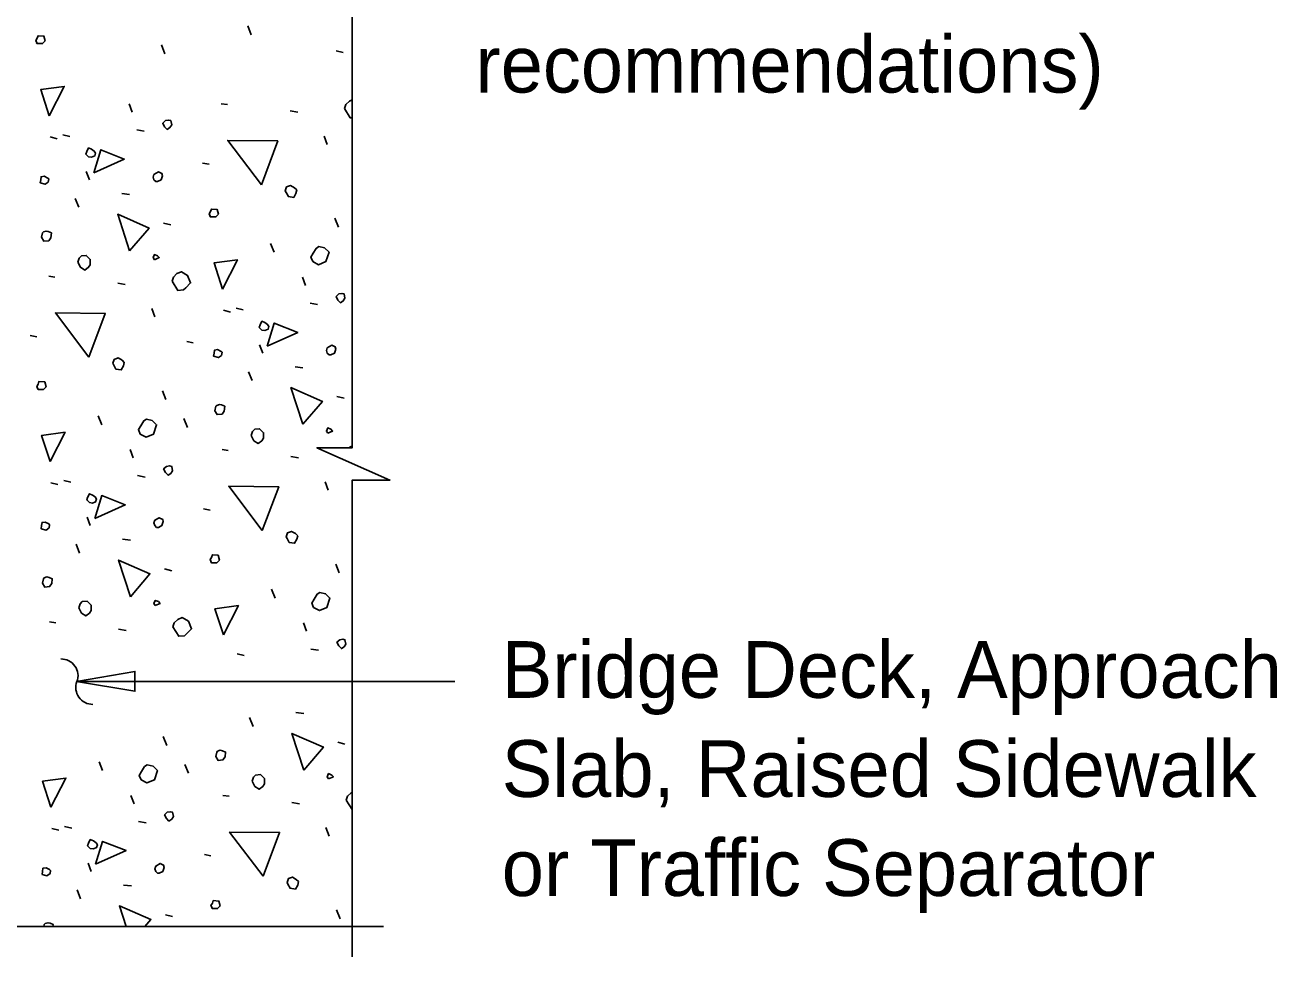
# Model space of a CAD drawing. Extents: x 0 to 15.4, y 0 to 9.7.
# Drawn here: x 5 to 6.668, y 1.924 to 3.173 of the extents above; entities that cross this region are included whole.
import ezdxf

# ---------------------------------------------------------------- set-up
doc = ezdxf.new("R2010")
doc.units = 0
doc.layers.add('Dimension', color=7, linetype='Continuous')
doc.layers.add('Miscellaneous', color=7, linetype='Continuous')

msp = doc.modelspace()

# ---------------------------------------------------------------- linework, layer by layer
at = {"layer": 'Dimension'}
msp.add_line((5.5721, 2.2981), (5.0679, 2.2981), dxfattribs=at)
for points in [[(5.4356, 3.1456), (5.4356, 3.4469), (5.4858, 3.4469), (5.3885, 3.49), (5.4356, 3.49), (5.4356, 4.0864)], [(5.4356, 1.931), (5.4356, 2.5663), (5.4858, 2.5663), (5.3885, 2.6094), (5.4356, 2.6094), (5.4356, 3.1456)], [(5.477, 1.9713), (4.8318, 1.9713), (4.8318, 2.0215), (4.7887, 1.9242), (4.7887, 1.9713), (4.2134, 1.9713)]]:
    msp.add_lwpolyline(points, dxfattribs=at)
msp.add_lwpolyline([(5.0679, 2.2981), (5.146, 2.2849), (5.146, 2.3113)], close=True, dxfattribs=at)
for centre, start, end in [((5.0477, 2.3056), 339.2893, 91.0165), ((5.0896, 2.2898), 159.2893, 271.0165)]:
    msp.add_arc(centre, 0.0224, start, end, dxfattribs=at)
at = {"layer": 'Miscellaneous'}
for p, q in [((5.3009, 3.1597), (5.2962, 3.1715)), ((5.186, 3.1344), (5.1813, 3.1462)), ((5.4141, 3.1385), (5.4235, 3.1361)), ((5.1424, 3.0566), (5.1383, 3.0678)), ((5.2608, 3.0678), (5.2691, 3.0666)), ((5.3528, 3.0584), (5.3628, 3.0566)), ((5.0328, 3.0236), (5.0422, 3.0212)), ((5.0499, 3.0265), (5.0593, 3.0242)), ((5.1483, 3.033), (5.1583, 3.0312)), ((5.4023, 3.0136), (5.3981, 3.0248)), ((5.2361, 2.9888), (5.2449, 2.9871)), ((5.0852, 2.9664), (5.0811, 2.9776)), ((5.0711, 2.9299), (5.0664, 2.9417)), ((5.1283, 2.9482), (5.1389, 2.947)), ((5.1842, 2.9087), (5.1937, 2.9063)), ((5.417, 2.9034), (5.4123, 2.9152)), ((5.3316, 2.8698), (5.3268, 2.8816)), ((5.031, 2.838), (5.0393, 2.8368)), ((5.3734, 2.8256), (5.3693, 2.8368)), ((5.123, 2.8285), (5.133, 2.8268)), ((5.1725, 2.7838), (5.1683, 2.795)), ((5.2638, 2.7926), (5.2732, 2.7902)), ((5.2809, 2.7955), (5.2903, 2.7932)), ((5.3793, 2.802), (5.3893, 2.8003)), ((5.0063, 2.759), (5.0151, 2.7572)), ((5.2149, 2.7508), (5.2237, 2.749)), ((5.3162, 2.7354), (5.3121, 2.7466)), ((5.3021, 2.6989), (5.2974, 2.7107)), ((5.3593, 2.7172), (5.3699, 2.716)), ((5.1872, 2.6736), (5.1825, 2.6854)), ((5.4152, 2.6777), (5.4247, 2.6753)), ((5.1017, 2.64), (5.097, 2.6518)), ((5.2161, 2.6364), (5.2113, 2.6482)), ((5.1436, 2.5958), (5.1395, 2.607)), ((5.262, 2.607), (5.2703, 2.6058)), ((5.3539, 2.5976), (5.364, 2.5958)), ((5.1495, 2.5722), (5.1595, 2.5704)), ((5.034, 2.5628), (5.0434, 2.5604)), ((5.0511, 2.5657), (5.0605, 2.5634)), ((5.4034, 2.5528), (5.3993, 2.564)), ((5.2373, 2.528), (5.2461, 2.5263)), ((5.0864, 2.5056), (5.0823, 2.5168)), ((5.1294, 2.4874), (5.14, 2.4862)), ((5.0723, 2.4691), (5.0676, 2.4809)), ((5.4182, 2.4426), (5.4135, 2.4544)), ((5.1854, 2.4479), (5.1949, 2.4455)), ((5.3327, 2.409), (5.328, 2.4208)), ((5.0322, 2.3772), (5.0405, 2.376)), ((5.3746, 2.3648), (5.3704, 2.376)), ((5.1241, 2.3677), (5.1342, 2.366)), ((5.3805, 2.3412), (5.3905, 2.3395)), ((5.2821, 2.3347), (5.2915, 2.3324)), ((5.3604, 2.2564), (5.371, 2.2552)), ((5.3033, 2.2381), (5.2986, 2.2499)), ((5.1884, 2.2128), (5.1837, 2.2246)), ((5.4164, 2.2169), (5.4258, 2.2145)), ((5.1029, 2.1792), (5.0982, 2.191)), ((5.2172, 2.1756), (5.2125, 2.1874)), ((5.1448, 2.135), (5.1406, 2.1462)), ((5.2632, 2.1462), (5.2715, 2.145)), ((5.3551, 2.1368), (5.3651, 2.135)), ((5.0352, 2.102), (5.0446, 2.0996)), ((5.0523, 2.1049), (5.0617, 2.1026)), ((5.1507, 2.1114), (5.1607, 2.1097)), ((5.4046, 2.092), (5.4005, 2.1032)), ((5.0876, 2.0448), (5.0835, 2.056)), ((5.2385, 2.0672), (5.2473, 2.0655)), ((5.0735, 2.0083), (5.0688, 2.0201)), ((5.1306, 2.0266), (5.1412, 2.0254)), ((5.1866, 1.9871), (5.196, 1.9847)), ((5.4194, 1.9818), (5.4146, 1.9936))]:
    msp.add_line(p, q, dxfattribs=at)
for points in [[(5.0157, 3.1479), (5.0228, 3.1479), (5.0263, 3.1515), (5.0246, 3.1579), (5.0169, 3.1585), (5.0157, 3.155), (5.0139, 3.152), (5.0157, 3.1479), (5.0145, 3.1491)], [(5.0316, 3.0519), (5.0204, 3.0866), (5.0517, 3.0908), (5.0316, 3.0519)], [(5.4356, 3.0729), (5.4317, 3.0713), (5.427, 3.0666), (5.4252, 3.0613)], [(5.4252, 3.0613), (5.4329, 3.0489), (5.4356, 3.0491)], [(5.1854, 3.0371), (5.189, 3.0336), (5.1925, 3.036), (5.1949, 3.0395), (5.1937, 3.0454), (5.1907, 3.046), (5.1866, 3.0454), (5.1831, 3.0419), (5.1854, 3.0371)], [(5.0841, 2.9971), (5.0882, 2.9965), (5.0923, 2.9982), (5.0935, 3.0018), (5.0917, 3.0047), (5.0882, 3.0071), (5.0841, 3.0089), (5.0817, 3.0041), (5.0805, 3.0006), (5.0841, 2.9971)], [(5.0911, 2.9759), (5.1006, 3.0065), (5.1318, 2.9941), (5.0911, 2.9759)], [(5.3145, 2.9599), (5.2697, 3.0189), (5.3363, 3.0183), (5.3145, 2.9599)], [(5.0198, 2.9623), (5.0263, 2.9605), (5.0304, 2.9635), (5.031, 2.9676), (5.0299, 2.9688), (5.0251, 2.9711), (5.021, 2.9706), (5.0204, 2.9664), (5.0198, 2.9623)], [(5.1736, 2.9641), (5.176, 2.9641), (5.1807, 2.9664), (5.1825, 2.9717), (5.1819, 2.9747), (5.1772, 2.977), (5.1713, 2.9735), (5.1701, 2.97), (5.1713, 2.9664), (5.1736, 2.9641)], [(5.3475, 2.9493), (5.3504, 2.944), (5.3575, 2.9429), (5.3604, 2.9482), (5.3616, 2.9529), (5.3587, 2.9558), (5.3534, 2.9588), (5.3481, 2.957), (5.3463, 2.9517), (5.3475, 2.9493)], [(5.1389, 2.8716), (5.123, 2.9205), (5.1648, 2.9022), (5.1389, 2.8716)], [(5.2467, 2.9169), (5.2538, 2.9169), (5.2573, 2.9205), (5.2555, 2.9269), (5.2479, 2.9275), (5.2467, 2.924), (5.2449, 2.9211), (5.2467, 2.9169), (5.2455, 2.9181)], [(5.0216, 2.8898), (5.0246, 2.8845), (5.031, 2.8851), (5.034, 2.8892), (5.0346, 2.8957), (5.0304, 2.8975), (5.0275, 2.8981), (5.024, 2.8969), (5.0228, 2.8957), (5.0216, 2.8898)], [(5.3828, 2.8574), (5.3905, 2.8533), (5.4005, 2.8574), (5.4046, 2.8698), (5.3987, 2.8757), (5.3911, 2.8775), (5.3875, 2.8751), (5.3834, 2.8686), (5.3805, 2.8633), (5.3828, 2.8574)], [(5.0699, 2.8568), (5.0735, 2.8498), (5.0794, 2.8462), (5.0841, 2.8498), (5.0864, 2.8533), (5.0864, 2.8604), (5.0811, 2.8657), (5.0746, 2.8651), (5.0717, 2.8621), (5.0699, 2.8568)], [(5.1719, 2.8598), (5.1784, 2.8627), (5.176, 2.8651), (5.1719, 2.8668), (5.1701, 2.8627), (5.1719, 2.8598)], [(5.2626, 2.8209), (5.2514, 2.8556), (5.2826, 2.8598), (5.2626, 2.8209)], [(5.1954, 2.8315), (5.2031, 2.8191), (5.2108, 2.8197), (5.2137, 2.8227), (5.2202, 2.8291), (5.2161, 2.8391), (5.2078, 2.8439), (5.2019, 2.8415), (5.1972, 2.8368), (5.1954, 2.8315)], [(5.4164, 2.8062), (5.4199, 2.8026), (5.4235, 2.805), (5.4258, 2.8085), (5.4247, 2.8144), (5.4217, 2.815), (5.4176, 2.8144), (5.4141, 2.8109), (5.4164, 2.8062)], [(5.0847, 2.7301), (5.0399, 2.7891), (5.1065, 2.7885), (5.0847, 2.7301)], [(5.3151, 2.7661), (5.3192, 2.7655), (5.3233, 2.7673), (5.3245, 2.7708), (5.3227, 2.7737), (5.3192, 2.7761), (5.3151, 2.7779), (5.3127, 2.7732), (5.3115, 2.7696), (5.3151, 2.7661)], [(5.3221, 2.7449), (5.3316, 2.7755), (5.3628, 2.7631), (5.3221, 2.7449)], [(5.2508, 2.7313), (5.2573, 2.7295), (5.2614, 2.7325), (5.262, 2.7366), (5.2608, 2.7378), (5.2561, 2.7402), (5.252, 2.7396), (5.2514, 2.7354), (5.2508, 2.7313)], [(5.4046, 2.7331), (5.407, 2.7331), (5.4117, 2.7354), (5.4135, 2.7407), (5.4129, 2.7437), (5.4082, 2.746), (5.4023, 2.7425), (5.4011, 2.739), (5.4023, 2.7354), (5.4046, 2.7331)], [(5.1177, 2.7195), (5.1206, 2.7142), (5.1277, 2.713), (5.1306, 2.7184), (5.1318, 2.7231), (5.1289, 2.726), (5.1236, 2.729), (5.1182, 2.7272), (5.1165, 2.7219), (5.1177, 2.7195)], [(5.0169, 2.6871), (5.024, 2.6871), (5.0275, 2.6907), (5.0257, 2.6971), (5.0181, 2.6977), (5.0169, 2.6942), (5.0151, 2.6912), (5.0169, 2.6871), (5.0157, 2.6883)], [(5.3699, 2.6406), (5.3539, 2.6895), (5.3958, 2.6712), (5.3699, 2.6406)], [(5.2526, 2.6588), (5.2555, 2.6535), (5.262, 2.6541), (5.265, 2.6582), (5.2656, 2.6647), (5.2614, 2.6665), (5.2585, 2.6671), (5.255, 2.6659), (5.2538, 2.6647), (5.2526, 2.6588)], [(5.153, 2.6276), (5.1607, 2.6235), (5.1707, 2.6276), (5.1748, 2.64), (5.1689, 2.6459), (5.1613, 2.6476), (5.1577, 2.6453), (5.1536, 2.6388), (5.1507, 2.6335), (5.153, 2.6276)], [(5.4029, 2.6288), (5.4093, 2.6317), (5.407, 2.6341), (5.4029, 2.6359), (5.4011, 2.6317), (5.4029, 2.6288)], [(5.0328, 2.5911), (5.0216, 2.6258), (5.0528, 2.63), (5.0328, 2.5911)], [(5.3009, 2.6258), (5.3045, 2.6188), (5.3103, 2.6152), (5.3151, 2.6188), (5.3174, 2.6223), (5.3174, 2.6294), (5.3121, 2.6347), (5.3056, 2.6341), (5.3027, 2.6311), (5.3009, 2.6258)], [(5.4356, 2.6116), (5.4329, 2.6105), (5.4318, 2.6094)], [(5.1866, 2.5763), (5.1901, 2.5728), (5.1937, 2.5752), (5.196, 2.5787), (5.1949, 2.5846), (5.1919, 2.5852), (5.1878, 2.5846), (5.1842, 2.5811), (5.1866, 2.5763)], [(5.3156, 2.4991), (5.2709, 2.5581), (5.3375, 2.5575), (5.3156, 2.4991)], [(5.0852, 2.5363), (5.0894, 2.5357), (5.0935, 2.5375), (5.0947, 2.541), (5.0929, 2.5439), (5.0894, 2.5463), (5.0852, 2.5481), (5.0829, 2.5433), (5.0817, 2.5398), (5.0852, 2.5363)], [(5.0923, 2.5151), (5.1017, 2.5457), (5.133, 2.5333), (5.0923, 2.5151)], [(5.021, 2.5015), (5.0275, 2.4997), (5.0316, 2.5027), (5.0322, 2.5068), (5.031, 2.508), (5.0263, 2.5103), (5.0222, 2.5098), (5.0216, 2.5056), (5.021, 2.5015)], [(5.1748, 2.5033), (5.1772, 2.5033), (5.1819, 2.5056), (5.1837, 2.5109), (5.1831, 2.5139), (5.1784, 2.5162), (5.1725, 2.5127), (5.1713, 2.5092), (5.1725, 2.5056), (5.1748, 2.5033)], [(5.3486, 2.4885), (5.3516, 2.4832), (5.3587, 2.4821), (5.3616, 2.4874), (5.3628, 2.4921), (5.3598, 2.495), (5.3545, 2.498), (5.3492, 2.4962), (5.3475, 2.4909), (5.3486, 2.4885)], [(5.14, 2.4108), (5.1241, 2.4597), (5.166, 2.4414), (5.14, 2.4108)], [(5.2479, 2.4561), (5.255, 2.4561), (5.2585, 2.4597), (5.2567, 2.4662), (5.2491, 2.4667), (5.2479, 2.4632), (5.2461, 2.4603), (5.2479, 2.4561), (5.2467, 2.4573)], [(5.0228, 2.429), (5.0257, 2.4237), (5.0322, 2.4243), (5.0352, 2.4284), (5.0358, 2.4349), (5.0316, 2.4367), (5.0287, 2.4373), (5.0251, 2.4361), (5.024, 2.4349), (5.0228, 2.429)], [(5.0711, 2.396), (5.0746, 2.389), (5.0805, 2.3854), (5.0852, 2.389), (5.0876, 2.3925), (5.0876, 2.3996), (5.0823, 2.4049), (5.0758, 2.4043), (5.0729, 2.4013), (5.0711, 2.396)], [(5.173, 2.399), (5.1795, 2.4019), (5.1772, 2.4043), (5.173, 2.406), (5.1713, 2.4019), (5.173, 2.399)], [(5.384, 2.3966), (5.3917, 2.3925), (5.4017, 2.3966), (5.4058, 2.409), (5.3999, 2.4149), (5.3923, 2.4167), (5.3887, 2.4143), (5.3846, 2.4078), (5.3816, 2.4025), (5.384, 2.3966)], [(5.2638, 2.3601), (5.2526, 2.3949), (5.2838, 2.399), (5.2638, 2.3601)], [(5.1966, 2.3707), (5.2043, 2.3583), (5.2119, 2.3589), (5.2149, 2.3619), (5.2214, 2.3683), (5.2172, 2.3784), (5.209, 2.3831), (5.2031, 2.3807), (5.1984, 2.376), (5.1966, 2.3707)], [(5.4176, 2.3454), (5.4211, 2.3418), (5.4247, 2.3442), (5.427, 2.3477), (5.4258, 2.3536), (5.4229, 2.3542), (5.4188, 2.3536), (5.4152, 2.3501), (5.4176, 2.3454)], [(5.371, 2.1798), (5.3551, 2.2287), (5.397, 2.2104), (5.371, 2.1798)], [(5.2538, 2.198), (5.2567, 2.1927), (5.2632, 2.1933), (5.2662, 2.1975), (5.2667, 2.2039), (5.2626, 2.2057), (5.2597, 2.2063), (5.2561, 2.2051), (5.255, 2.2039), (5.2538, 2.198)], [(5.1542, 2.1668), (5.1619, 2.1627), (5.1719, 2.1668), (5.176, 2.1792), (5.1701, 2.1851), (5.1624, 2.1868), (5.1589, 2.1845), (5.1548, 2.178), (5.1518, 2.1727), (5.1542, 2.1668)], [(5.034, 2.1303), (5.0228, 2.165), (5.054, 2.1692), (5.034, 2.1303)], [(5.3021, 2.165), (5.3056, 2.158), (5.3115, 2.1544), (5.3162, 2.158), (5.3186, 2.1615), (5.3186, 2.1686), (5.3133, 2.1739), (5.3068, 2.1733), (5.3039, 2.1703), (5.3021, 2.165)], [(5.404, 2.168), (5.4105, 2.1709), (5.4082, 2.1733), (5.404, 2.1751), (5.4023, 2.1709), (5.404, 2.168)], [(5.4356, 2.1503), (5.4341, 2.1497), (5.4294, 2.145), (5.4276, 2.1397)], [(5.4276, 2.1397), (5.4353, 2.1273), (5.4356, 2.1274)], [(5.1878, 2.1155), (5.1913, 2.112), (5.1949, 2.1144), (5.1972, 2.1179), (5.196, 2.1238), (5.1931, 2.1244), (5.189, 2.1238), (5.1854, 2.1203), (5.1878, 2.1155)], [(5.0864, 2.0755), (5.0906, 2.0749), (5.0947, 2.0767), (5.0959, 2.0802), (5.0941, 2.0831), (5.0906, 2.0855), (5.0864, 2.0873), (5.0841, 2.0825), (5.0829, 2.079), (5.0864, 2.0755)], [(5.3168, 2.0384), (5.272, 2.0973), (5.3386, 2.0967), (5.3168, 2.0384)], [(5.0935, 2.0543), (5.1029, 2.0849), (5.1342, 2.0725), (5.0935, 2.0543)], [(5.176, 2.0425), (5.1784, 2.0425), (5.1831, 2.0448), (5.1848, 2.0501), (5.1842, 2.0531), (5.1795, 2.0554), (5.1736, 2.0519), (5.1725, 2.0484), (5.1736, 2.0448), (5.176, 2.0425)], [(5.0222, 2.0407), (5.0287, 2.0389), (5.0328, 2.0419), (5.0334, 2.046), (5.0322, 2.0472), (5.0275, 2.0495), (5.0234, 2.049), (5.0228, 2.0448), (5.0222, 2.0407)], [(5.3498, 2.0277), (5.3528, 2.0224), (5.3598, 2.0213), (5.3628, 2.0266), (5.364, 2.0313), (5.361, 2.0342), (5.3557, 2.0372), (5.3504, 2.0354), (5.3486, 2.0301), (5.3498, 2.0277)], [(5.2491, 1.9953), (5.2561, 1.9953), (5.2597, 1.9989), (5.2579, 2.0054), (5.2502, 2.0059), (5.2491, 2.0024), (5.2473, 1.9995), (5.2491, 1.9953), (5.2479, 1.9965)], [(5.1343, 1.9713), (5.1253, 1.9989), (5.1672, 1.9806), (5.1593, 1.9713)], [(5.0367, 1.9713), (5.0369, 1.9741), (5.0328, 1.9759), (5.0299, 1.9765), (5.0263, 1.9753), (5.0251, 1.9741), (5.0246, 1.9713)]]:
    msp.add_lwpolyline(points, dxfattribs=at)

# ---------------------------------------------------------------- texts
at = {"layer": 'Dimension'}
for s, p in [('recommendations)', (5.5997, 3.0827)), ('Bridge Deck, Approach ', (5.6347, 2.2761)), ('Slab, Raised Sidewalk', (5.6347, 2.1441)), ('or Traffic Separator', (5.6347, 2.0121))]:
    msp.add_text(s, height=0.0756, dxfattribs=at).set_placement(p)

doc.saveas('drawing.dxf')
